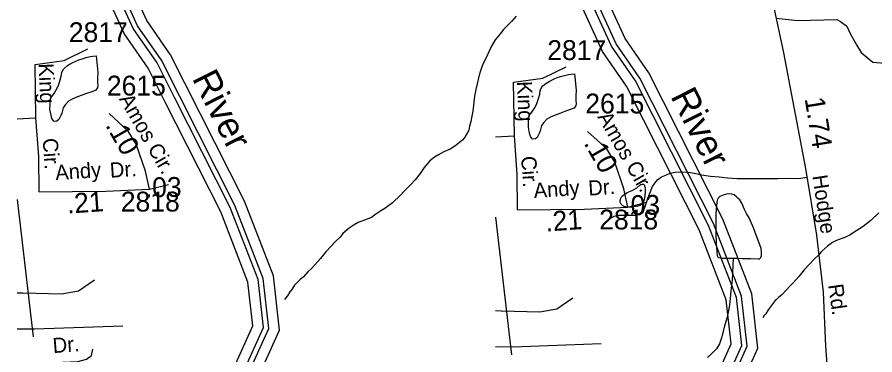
# Model space of a CAD drawing. Extents: x 2169602 to 2449496, y 721995 to 810662.
# Drawn here: x 2379098 to 2384505, y 789338 to 791467 of the extents above; entities that cross this region are included whole.
import ezdxf

# ---------------------------------------------------------------- set-up
doc = ezdxf.new("R2010")
doc.units = 0
doc.layers.add('Default', color=7, linetype='Continuous')

msp = doc.modelspace()

# ---------------------------------------------------------------- linework, layer by layer
at = {"layer": 'Default'}
for p, q in [((2379098.1, 790318.1), (2379199.2, 789451.9)), ((2382114, 790205.3), (2382215, 789339.1))]:
    msp.add_line(p, q, dxfattribs=at)
for points in [[(2379983.2, 787503.2), (2380007.4, 787553.6), (2380015.5, 787762), (2380071.3, 787892.4), (2380087.5, 788035.6), (2380214.4, 788389.2), (2380486.1, 788905.7), (2380751.2, 789493.9), (2380713.5, 789835.9), (2380531.2, 790306), (2380064.8, 791229.6), (2379914.9, 791444.6), (2379768.4, 791766.8), (2379516.9, 792626.4), (2379438.8, 792880.6), (2379340.2, 793084.5), (2379304.5, 793156.8), (2379281.3, 793221.8)], [(2380090.1, 790961.2), (2379980.1, 791179), (2379829, 791395.6), (2379675.9, 791732.5), (2379422.6, 792598.1), (2379346.9, 792844.5), (2379251.7, 793041.3), (2379186, 793174.5)], [(2379917.5, 787518.1), (2379942.4, 787569.7), (2379950.4, 787776.6), (2380007.2, 787909.4), (2380023.2, 788050.6), (2380154.2, 788415.7), (2380427.1, 788934.4), (2380684, 789504.5), (2380649.2, 789820.2), (2380471.2, 790279.3), (2380008.3, 791195.8), (2379857.6, 791412), (2379706.8, 791743.9), (2379454, 792607.6), (2379377.5, 792856.5), (2379281.2, 793055.7), (2379244, 793131.1), (2379216.4, 793208.2)], [(2380031.5, 790931.6), (2379923.6, 791145.3), (2379771.7, 791363), (2379614.3, 791709.6), (2379359.7, 792579.3), (2379285.7, 792820.4), (2379192.8, 793012.5), (2379121.4, 793157)], [(2382999.1, 787390.4), (2383023.3, 787440.8), (2383031.3, 787649.1), (2383087.1, 787779.6), (2383103.4, 787922.8), (2383230.3, 788276.4), (2383501.9, 788792.8), (2383767, 789381.1), (2383729.3, 789723), (2383547, 790193.1), (2383080.6, 791116.7), (2382930.7, 791331.7), (2382784.3, 791654), (2382532.7, 792513.6), (2382454.6, 792767.7), (2382356, 792971.7), (2382320.3, 793044), (2382297.1, 793109)], [(2383105.9, 790848.4), (2382995.9, 791066.2), (2382844.8, 791282.8), (2382691.8, 791619.6), (2382438.4, 792485.3), (2382362.7, 792731.6), (2382267.6, 792928.5), (2382201.8, 793061.6)], [(2382933.4, 787405.2), (2382958.2, 787456.9), (2382966.2, 787663.8), (2383023, 787796.5), (2383039, 787937.7), (2383170.1, 788302.9), (2383442.9, 788821.6), (2383699.8, 789391.7), (2383665, 789707.3), (2383487, 790166.4), (2383024.2, 791083), (2382873.4, 791299.1), (2382722.6, 791631.1), (2382469.8, 792494.7), (2382393.4, 792743.7), (2382297, 792942.9), (2382259.8, 793018.3), (2382232.3, 793095.3)], [(2383047.3, 790818.8), (2382939.4, 791032.4), (2382787.5, 791250.2), (2382630.1, 791596.7), (2382375.6, 792466.4), (2382301.5, 792707.6), (2382208.6, 792899.7), (2382137.3, 793044.1)], [(2383770.1, 791990.8), (2383928.1, 791241), (2384067.3, 790512.2), (2384136.4, 790093.4), (2384179.3, 789733.2), (2384193.9, 789391.8), (2384222.2, 789000.2)], [(2382243.2, 791472.1), (2382213.7, 791440.1), (2382183.8, 791408.1), (2382164.3, 791387.9), (2382141.9, 791361.7), (2382112.2, 791323.6), (2382088.2, 791283.4), (2382072.4, 791247.7), (2382057, 791213.5), (2382033, 791169.3), (2382020.9, 791135.4), (2382011.5, 791101.1), (2381997.4, 791047.3), (2381989.6, 791011.1), (2381981.8, 790969.3), (2381977.9, 790933), (2381974, 790909.3), (2381970.1, 790873.3), (2381964.1, 790843), (2381958.6, 790809), (2381950.6, 790779), (2381944.5, 790755.1), (2381934.8, 790735.1), (2381921.1, 790709.2), (2381906.9, 790693.1), (2381877, 790668.8), (2381857.3, 790652.7), (2381827.2, 790634.5), (2381787.2, 790616.7), (2381749.2, 790596.5), (2381729.6, 790584.4), (2381699.4, 790560.2), (2381663.5, 790518.1), (2381638.1, 790481.8), (2381606.3, 790441.6), (2381576.4, 790407.6), (2381536.4, 790367.4), (2381514.5, 790345.2), (2381464.4, 790297.2), (2381415, 790260.8), (2381391.2, 790245), (2381359.2, 790224.6), (2381331.4, 790204.6), (2381303.5, 790192.6), (2381247.3, 790172.3), (2381221.6, 790158.3), (2381191.5, 790136.1), (2381151.9, 790101.9), (2381135.7, 790081.6), (2381103.9, 790051.6), (2381076.5, 790021.6), (2381044.5, 789987.6), (2381010.7, 789945.2), (2380974.6, 789905.2), (2380952.6, 789883), (2380931.1, 789861.1), (2380902.8, 789828.9), (2380882.7, 789812.9), (2380869.2, 789800.7), (2380861, 789792.6), (2380847.4, 789776.8), (2380829.4, 789750.7), (2380817.5, 789734.7), (2380801.5, 789710.4), (2380789.8, 789696.3), (2380783.5, 789686.3)], [(2383882.1, 791459.3), (2384016.9, 791445.1), (2384264.2, 791452.3), (2384289.3, 791439.7), (2384327.5, 791409.5), (2384350.2, 791364.2), (2384389, 791292.9), (2384418.1, 791244.4), (2384469.9, 791202.3), (2384492.9, 791182.7), (2384568.1, 791176.5), (2384659, 791201.5), (2384724.8, 791207.8), (2384787.5, 791239.1), (2384928.4, 791339.4), (2385035, 791389.6), (2385088.2, 791405.3), (2385147.8, 791405.3), (2385169.7, 791405.3)], [(2379216.8, 790831.6), (2379211, 791168.8), (2379395.2, 791193.9), (2379542.7, 791267.2)], [(2379595.6, 791222.8), (2379605.8, 791118.7), (2379603.8, 791080.8), (2379603.8, 791054.9), (2379606, 791033.1), (2379604.4, 791022.8), (2379594.6, 791006.8), (2379568.1, 790996.6), (2379534.3, 790984.7), (2379502.5, 790972.5), (2379468.7, 790960.2), (2379444.5, 790950), (2379420.9, 790936.2), (2379403, 790916.1), (2379388.7, 790896), (2379379.3, 790862.2), (2379373.1, 790846.1), (2379367.2, 790834), (2379363.5, 790826), (2379361.4, 790821.9), (2379349.1, 790811.9), (2379331.3, 790809.8), (2379317.3, 790827.7), (2379313, 790847.8), (2379304.8, 790885.6), (2379306.7, 790919.8), (2379308.7, 790947.5), (2379310.4, 790959.8), (2379320.4, 790971.6), (2379330.5, 790985.9), (2379344.8, 791007.7), (2379358.3, 791035.7), (2379369.8, 791072), (2379376.2, 791093.8), (2379380.1, 791118), (2379387.9, 791135.8), (2379395.9, 791146), (2379416, 791162), (2379435.9, 791174), (2379471.5, 791192.1), (2379493.3, 791200.2), (2379515.6, 791206.6), (2379533.5, 791212.4), (2379557.4, 791218.5), (2379575.3, 791220.6), (2379595.6, 791222.8)], [(2382232.6, 790718.8), (2382226.8, 791055.9), (2382411, 791081.1), (2382558.5, 791154.4)], [(2382611.4, 791110), (2382621.7, 791005.8), (2382619.6, 790968), (2382619.6, 790942.1), (2382621.9, 790920.2), (2382620.2, 790909.9), (2382610.4, 790894), (2382583.9, 790883.8), (2382550.1, 790871.9), (2382518.3, 790859.6), (2382484.5, 790847.3), (2382460.3, 790837.2), (2382436.7, 790823.3), (2382418.9, 790803.3), (2382404.5, 790783.2), (2382395.1, 790749.3), (2382388.9, 790733.2), (2382383, 790721.1), (2382379.3, 790713.2), (2382377.2, 790709), (2382364.9, 790699.1), (2382347.1, 790696.9), (2382333.2, 790714.9), (2382328.9, 790735), (2382320.6, 790772.7), (2382322.5, 790806.9), (2382324.5, 790834.6), (2382326.2, 790846.9), (2382336.2, 790858.8), (2382346.3, 790873.1), (2382360.6, 790894.9), (2382374.2, 790922.8), (2382385.7, 790959.2), (2382392, 790981), (2382395.9, 791005.1), (2382403.7, 791023), (2382411.7, 791033.2), (2382431.8, 791049.2), (2382451.7, 791061.2), (2382487.4, 791079.3), (2382509.1, 791087.4), (2382531.4, 791093.8), (2382549.3, 791099.6), (2382573.3, 791105.7), (2382591.1, 791107.8), (2382611.4, 791110)], [(2379884.7, 787525.5), (2379909.9, 787577.8), (2379917.9, 787783.9), (2379975.1, 787917.8), (2379991, 788058.1), (2380124.1, 788429), (2380397.6, 788948.8), (2380650.4, 789509.8), (2380617.1, 789812.3), (2380441.2, 790265.9), (2380090.1, 790961.2)], [(2379819, 787540.3), (2379844.8, 787594), (2379852.8, 787798.6), (2379911, 787934.8), (2379926.7, 788073.1), (2380063.9, 788455.4), (2380338.6, 788977.6), (2380583.2, 789520.5), (2380552.8, 789796.6), (2380381.2, 790239.2), (2380031.5, 790931.6)], [(2379931.5, 790382.4), (2379906.9, 790496.5), (2379849.3, 790665.1), (2379798.6, 790748.9), (2379677.2, 790858.8)], [(2382900.5, 787412.6), (2382925.7, 787465), (2382933.7, 787671.1), (2382990.9, 787805), (2383006.9, 787945.2), (2383140, 788316.1), (2383413.4, 788836), (2383666.2, 789397), (2383632.9, 789699.5), (2383457, 790153.1), (2383105.9, 790848.4)], [(2379098.1, 790826.1), (2379216.8, 790831.6)], [(2379236.1, 790365.6), (2379234.6, 790587.6), (2379216.8, 790831.6)], [(2382834.8, 787427.4), (2382860.7, 787481.1), (2382868.6, 787685.8), (2382926.8, 787822), (2382942.5, 787960.2), (2383079.7, 788342.6), (2383354.4, 788864.8), (2383599, 789407.6), (2383568.6, 789683.8), (2383397, 790126.4), (2383047.3, 790818.8)], [(2382947.3, 790269.6), (2382922.7, 790383.7), (2382865.1, 790552.3), (2382814.4, 790636.1), (2382693, 790746)], [(2382114, 790713.3), (2382232.6, 790718.8)], [(2382252, 790252.8), (2382250.4, 790474.8), (2382232.6, 790718.8)], [(2382823.5, 790192.1), (2382862, 790213), (2382887.7, 790217.8), (2382937.4, 790217.8), (2382995.1, 790217.8), (2383022.4, 790222.6), (2383044.8, 790237.1), (2383080.1, 790341.4), (2383102.6, 790399.1), (2383117, 790420), (2383136.2, 790444.1), (2383160.3, 790460.1), (2383192.4, 790473), (2383215.1, 790482.6), (2383245.3, 790489), (2383285.4, 790492.2), (2383323.9, 790489), (2383367.2, 790484.2), (2383412.1, 790473), (2383468.2, 790464.9), (2383522.7, 790460.1), (2383577.2, 790453.7), (2383636.6, 790450.5), (2383707.1, 790448.9), (2383787.3, 790450.5), (2383826.1, 790448.9), (2383891.9, 790450.5), (2383935.2, 790452.1), (2384005.7, 790450.5), (2384037.8, 790452.1), (2384076.2, 790458)], [(2379931.5, 790382.4), (2380051.3, 790412.8)], [(2382998.6, 790273.6), (2382972.4, 790269.8), (2382946.5, 790267.7), (2382934.4, 790271.5), (2382924.2, 790273.5), (2382916.4, 790277.5), (2382906.6, 790287.5), (2382900.4, 790299.4), (2382900.2, 790311.2), (2382904.3, 790325.5), (2382908.2, 790333.5), (2382914.4, 790339.5), (2382922.1, 790347.6), (2382934.4, 790355.5), (2382944.1, 790361.8), (2382974, 790373.8), (2383003.8, 790391.7), (2383024.1, 790408.1), (2383029.8, 790412.1), (2383037.8, 790414.1), (2383041.5, 790413.9), (2383047.4, 790413.9), (2383051.9, 790407.9), (2383053.8, 790404), (2383056.2, 790392.2), (2383057.9, 790382.2), (2383056, 790363.9), (2383051.9, 790325.9), (2383048, 790307.9), (2383043.9, 790295.9), (2383042.5, 790290.1), (2383038.4, 790287.9), (2383022.6, 790279.7), (2383010.5, 790275.9), (2382998.6, 790273.6)], [(2379236.1, 790365.6), (2379657.3, 790368.8), (2379931.5, 790382.4)], [(2383611.7, 789946.4), (2383643.7, 789946.8), (2383671.4, 789945.1), (2383721.6, 789945.2), (2383769.8, 789943.2), (2383777.4, 789943.2), (2383785.6, 789951.3), (2383789.7, 789963.3), (2383789.5, 789983.1), (2383787.7, 790009.4), (2383767.2, 790065.2), (2383751, 790109), (2383740.7, 790139), (2383712.4, 790200.9), (2383696.2, 790228.9), (2383683.9, 790254.7), (2383666.3, 790294.7), (2383654, 790314.8), (2383643.7, 790324.5), (2383632.2, 790334.7), (2383618.1, 790346.6), (2383603.7, 790350.3), (2383582, 790352.4), (2383569.9, 790350.2), (2383548, 790344.2), (2383527.9, 790336.3), (2383518.2, 790326), (2383510.4, 790312.2), (2383506.1, 790282), (2383502.2, 790227.8), (2383502.6, 790192), (2383502.9, 790162), (2383503.1, 790127.9), (2383502.9, 790102), (2383505.1, 790046), (2383509.6, 789986.2), (2383511.9, 789963.9), (2383513.5, 789956.3), (2383521.7, 789952.3), (2383539.8, 789948.3), (2383563.5, 789948.4), (2383603.7, 789946.4), (2383611.7, 789946.4)], [(2382947.3, 790269.6), (2383067.1, 790299.9)], [(2382252, 790252.8), (2382673.1, 790255.9), (2382947.3, 790269.6)], [(2384530.3, 790232.3), (2384480.3, 790184.4), (2384430.8, 790148), (2384407.1, 790132.2), (2384375.1, 790111.8), (2384347.2, 790091.7), (2384319.3, 790079.7), (2384263.1, 790059.4), (2384237.5, 790045.5), (2384207.3, 790023.2), (2384167.8, 789989.1), (2384151.6, 789968.8), (2384119.8, 789938.8), (2384092.3, 789908.8), (2384060.3, 789874.7), (2384026.5, 789832.4), (2383990.4, 789792.4), (2383968.4, 789770.1), (2383946.9, 789748.3), (2383918.6, 789716.1), (2383898.5, 789700), (2383885, 789687.9), (2383876.8, 789679.8), (2383863.3, 789664), (2383845.2, 789637.9), (2383833.3, 789621.9), (2383817.3, 789597.5), (2383805.6, 789583.5), (2383799.3, 789573.5)], [(2383611.7, 789946.4), (2383606.2, 789808.5), (2383596.2, 789740.6), (2383592.9, 789692.5), (2383589.2, 789652.4), (2383584.7, 789628.4), (2383573.2, 789574.6), (2383557.4, 789518.5), (2383537.9, 789444.4), (2383526, 789406.4), (2383506.1, 789376.2), (2383480.3, 789348.1), (2383450.4, 789322.2)], [(2379098.1, 789729.3), (2379133.6, 789728.4), (2379378, 789722.1), (2379484.5, 789740.9), (2379584.8, 789809.9)], [(2382114, 789616.5), (2382149.4, 789615.6), (2382393.8, 789609.3), (2382500.3, 789628.1), (2382600.6, 789697.1)], [(2379098.1, 789502.7), (2379208, 789501.6), (2379763.4, 789521.5)], [(2382114, 789389.9), (2382223.8, 789388.8), (2382779.2, 789408.7)], [(2379098.1, 789281.2), (2379196.3, 789283.3), (2379481.4, 789295.9), (2379534.6, 789311.6), (2379566, 789333.5), (2379575.4, 789374.2)]]:
    msp.add_lwpolyline(points, dxfattribs=at)

# ---------------------------------------------------------------- texts
for s, p in [('2817', (2379423.9, 791309.4)), ('2817', (2382439.8, 791196.6)), ('2615', (2379663.7, 790972.7)), ('2615', (2382679.6, 790859.8)), ('2818', (2379751.4, 790241.4)), ('2818', (2382767.3, 790128.6))]:
    msp.add_text(s, height=125, dxfattribs=at).set_placement(p)
for s, height, rotation, p in [('King', 95, 272.3334, (2379233, 791174.4)), ('River', 167.32, 296.7931, (2380198.4, 791081.3)), ('King', 95, 272.3334, (2382248.8, 791061.6)), ('River', 167.32, 296.7931, (2383214.2, 790968.5)), ('Amos Cir.', 95, 299.8372, (2379738.2, 790951)), ('1.74', 125, 279.2429, (2384062, 790953.3)), ('Amos Cir.', 95, 299.8372, (2382754, 790838.2)), ('.10', 125, 299.8372, (2379651.7, 790785.1)), ('Cir.', 95, 273.974, (2379258.8, 790701.1)), ('.10', 125, 299.8372, (2382667.5, 790672.3)), ('Cir.', 95, 273.974, (2382274.6, 790588.3)), ('Andy', 95, 3.9387, (2379341.4, 790439)), ('Dr.', 95, 3.7056, (2379685.3, 790454.3)), ('.03', 125, 0.9966, (2379903.7, 790330.4)), ('Hodge', 95, 278.5806, (2384110.7, 790465.7)), ('Andy', 95, 3.9387, (2382357.2, 790326.2)), ('Dr.', 95, 3.7056, (2382701.1, 790341.5)), ('.21', 125, 3.9387, (2379415.7, 790227.9)), ('.03', 125, 0.9966, (2382919.6, 790217.6)), ('.21', 125, 3.9387, (2382431.5, 790115)), ('Rd.', 95, 278.07, (2384210.1, 789778.6)), ('Dr.', 95, 4.5812, (2379325.6, 789348.6))]:
    msp.add_text(s, height=height, rotation=rotation, dxfattribs=at).set_placement(p)

doc.saveas('drawing.dxf')
